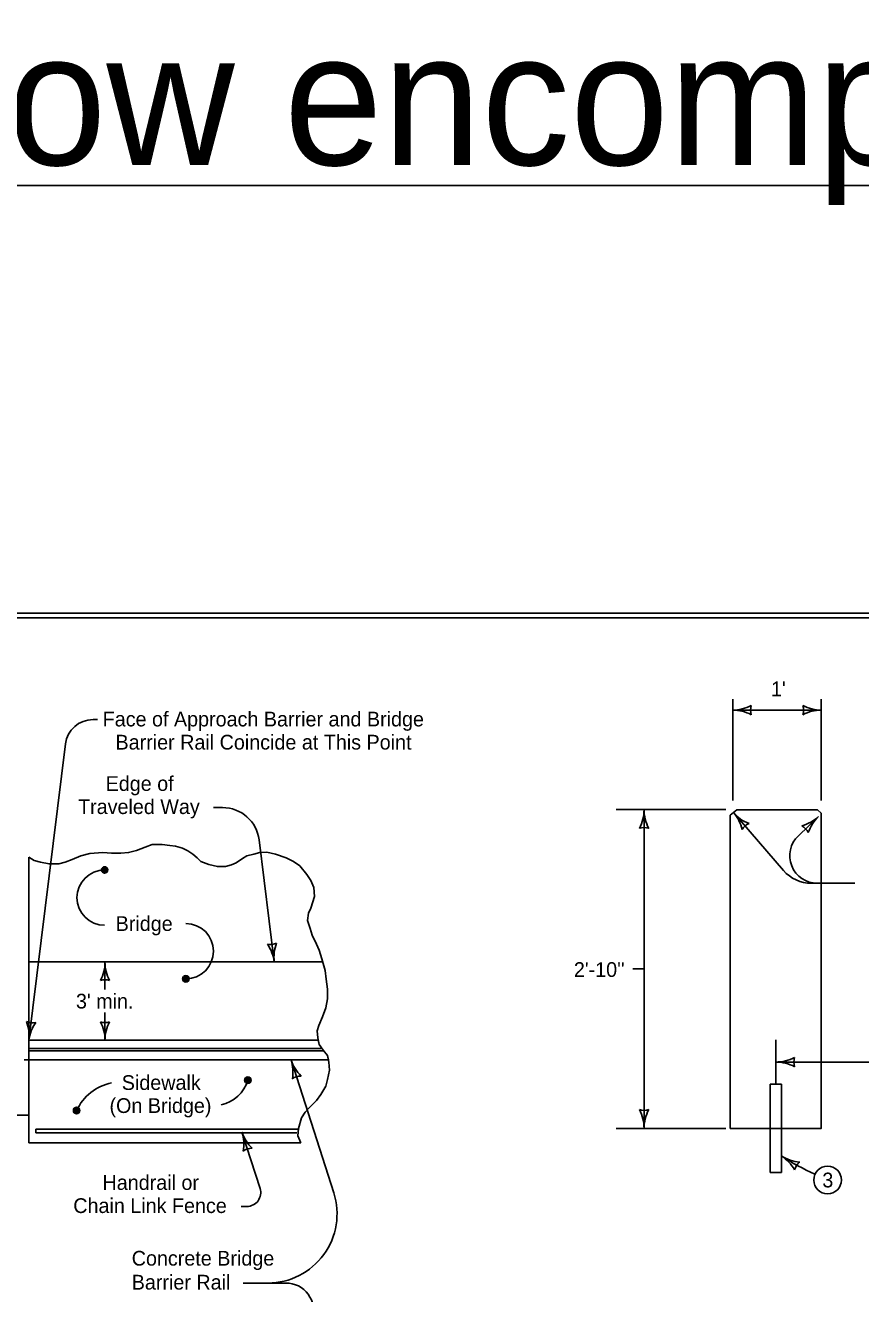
# Model space of a CAD drawing. Extents: x 10028 to 81668, y 6395 to 11634.
# Drawn here: x 11378 to 12284, y 9205 to 10582 of the extents above; entities that cross this region are included whole.
import ezdxf

# ---------------------------------------------------------------- set-up
doc = ezdxf.new("R2010")
doc.units = 0
for name, color, linetype in [('Default', 7, 'Continuous'), ('dsnCellElements', 7, 'Continuous'), ('dsnstdblockInterim', 7, 'Continuous'), ('dsnStdDimension', 7, 'Continuous'), ('dsnStdTextLabel', 7, 'Continuous'), ('ShtPlotIdentification', 7, 'Continuous')]:
    doc.layers.add(name, color=color, linetype=linetype)

msp = doc.modelspace()

# ---------------------------------------------------------------- linework, layer by layer
at = {"layer": 'Default'}
msp.add_lwpolyline([(10132.5, 9944), (13267.5, 9944), (13267.5, 7924), (10132.5, 7924)], close=True, dxfattribs=at)
msp.add_lwpolyline([(10132.5, 9944), (13267.5, 9944), (13267.5, 7924), (10132.5, 7924)], close=True, dxfattribs=at)
at = {"layer": 'dsnCellElements'}
for p, q in [((11381.7, 9459.2), (11381.7, 9480.5)), ((11381.7, 9480.5), (11695.7, 9480.5)), ((11706.6, 9459.2), (11381.7, 9459.2))]:
    msp.add_line(p, q, dxfattribs=at)
msp.add_lwpolyline([(12142.6, 9384.9), (12241.3, 9384.9), (12241.3, 9727), (12237.1, 9730.6), (12149.5, 9730.6), (12142.6, 9724.7)], close=True, dxfattribs=at)
msp.add_lwpolyline([(11695.7, 9480.5), (11696.7, 9476.1), (11700.8, 9469.7), (11705.5, 9463.9), (11706.6, 9459.2)], dxfattribs=at)
at = {"layer": 'dsnstdblockInterim'}
for points in [[(10132.5, 9944), (13267.5, 9944), (13267.5, 7924), (10132.5, 7924)], [(10132.5, 9939), (13267.5, 9939), (13267.5, 7929), (10132.5, 7929)]]:
    msp.add_lwpolyline(points, close=True, dxfattribs=at)
at = {"layer": 'dsnStdDimension'}
msp.add_lwpolyline([(10028, 7824.5), (13372, 7824.5), (13372, 10408.5), (10028, 10408.5)], close=True, dxfattribs=at)
at = {"layer": 'ShtPlotIdentification'}
for p, q in [((12145.3, 9740.9), (12145.3, 9850.9)), ((12241.3, 9740.9), (12241.3, 9850.9)), ((12241.3, 9838.9), (12145.3, 9838.9)), ((11456, 9828.6), (11451.3, 9828.6)), ((11381.7, 9480.5), (11421.6, 9802.3)), ((11591.8, 9733.1), (11582, 9733.1)), ((12137.9, 9730.9), (12018.9, 9730.9)), ((12049, 9384.9), (12049, 9730.9)), ((12142.6, 9724.7), (12149.5, 9730.6)), ((12142.6, 9384.9), (12142.6, 9724.7)), ((12146.1, 9727.7), (12200.3, 9664.8)), ((12237.1, 9730.6), (12149.5, 9730.6)), ((12238.2, 9723.4), (12216.4, 9702.6)), ((12241.3, 9727), (12237.1, 9730.6)), ((12241.3, 9384.9), (12241.3, 9727)), ((11647.9, 9565.5), (11631.5, 9698.1)), ((11381.7, 9679.2), (11381.7, 9459.2)), ((11381.7, 9679.2), (11381.7, 9459.2)), ((12277.7, 9650.9), (12230.6, 9650.9)), ((11381.7, 9565.5), (11700.6, 9565.5)), ((11464.3, 9535.5), (11464.3, 9565.5)), ((12049, 9557.9), (12037, 9557.9)), ((11464.3, 9480.5), (11464.3, 9510.5)), ((11381.7, 9480.5), (11695.7, 9480.5)), ((12192, 9480.9), (12192, 9432.9)), ((11376.7, 9459.2), (11706.6, 9459.2)), ((11381.7, 9471.7), (11698.4, 9471.7)), ((11381.7, 9469.2), (11700.9, 9469.2)), ((11381.7, 9369.2), (11381.7, 9459.2)), ((11666.2, 9459.2), (11712.4, 9314.9)), ((12306, 9456.9), (12192, 9456.9)), ((12186, 9432.9), (12198, 9432.9)), ((12186, 9432.9), (12186, 9336.9)), ((12198, 9432.9), (12198, 9336.9)), ((10687.5, 9399.2), (11381.7, 9399.2)), ((11389.2, 9384.2), (11674, 9384.2)), ((11389.2, 9380.2), (11389.2, 9384.2)), ((11389.2, 9380.2), (11672.3, 9380.2)), ((11612.9, 9380.8), (11632.5, 9319.7)), ((12137.9, 9384.9), (12018.9, 9384.9)), ((12142.6, 9384.9), (12241.3, 9384.9)), ((11381.7, 9369.2), (11676.7, 9369.2)), ((12186, 9336.9), (12198, 9336.9)), ((11612.1, 9300.1), (11618.2, 9300.1)), ((11660.5, 9217), (11614.1, 9217))]:
    msp.add_line(p, q, dxfattribs=at)
for points in [[(11676.7, 9369.2), (11673.5, 9376.7), (11674.1, 9384.8), (11677.6, 9396.5), (11681.6, 9402.3), (11686.9, 9408.1), (11693.8, 9415.1), (11698.5, 9421.5), (11703.7, 9430.8), (11705.5, 9437.8), (11707.8, 9448.2), (11707.2, 9456.9), (11705.5, 9463.9), (11700.8, 9469.7), (11696.7, 9476.1), (11695, 9483.1), (11694.4, 9490.7), (11696.2, 9496.5), (11700.2, 9505.8), (11703.7, 9515.7), (11705.5, 9525.5), (11705.5, 9536), (11704.3, 9547), (11703.1, 9556.3), (11699.6, 9569.1), (11696.7, 9578.4), (11693.8, 9584.8), (11689.2, 9594.7), (11686.9, 9601.7), (11684, 9610.4), (11685.1, 9618.5), (11687.4, 9623.8), (11691.5, 9636.6), (11690.9, 9646.5), (11687.4, 9654), (11683.4, 9660.4), (11675.8, 9669.7), (11668.8, 9674.4), (11660.7, 9678.4), (11649.1, 9682.5), (11639.8, 9684.8), (11632.2, 9684.2), (11625.8, 9682.5), (11618.3, 9680.8), (11613.6, 9677.8), (11606.6, 9673.2), (11601.4, 9670.9), (11595, 9669.1), (11586.3, 9669.1), (11577, 9671.5), (11568.3, 9674.4), (11564.2, 9678.4), (11559.5, 9682.5), (11554.3, 9686), (11548.5, 9688.9), (11540.9, 9691.2), (11534.5, 9691.8), (11526.4, 9693), (11515.4, 9693), (11507.8, 9690.1), (11498.5, 9686.6), (11489.8, 9684.2), (11481.6, 9683.7), (11471.2, 9683.7), (11461.9, 9684.2), (11447.9, 9683.1), (11438, 9680.8), (11428.7, 9676.7), (11421.2, 9673.8), (11414.2, 9672), (11403.7, 9672), (11394.4, 9673.8), (11387.5, 9675.5), (11381.7, 9679.2)], [(11463.7, 9662.2), (11464.9, 9662.8), (11466.7, 9663.3), (11467, 9665.2), (11466.8, 9666.8), (11465.6, 9668.3), (11463.9, 9668.2), (11462, 9667.9), (11461.1, 9666.5), (11461, 9664.9), (11462.1, 9662.9), (11463.4, 9662.7), (11465.3, 9663.2), (11466.8, 9664.4), (11466.7, 9666.1), (11465.5, 9667.5), (11463.9, 9667.7), (11462, 9667.3), (11461.8, 9666.3), (11461.4, 9665), (11462.3, 9663.5), (11463.6, 9663.5), (11465.1, 9663.8), (11466.2, 9664.6), (11465.7, 9666.2), (11464.5, 9667.1), (11463, 9667.1), (11462.6, 9666.3), (11462.1, 9665.4), (11462.9, 9664.1), (11464, 9663.9), (11465, 9664.4), (11465.1, 9665.5), (11464.5, 9666.3), (11463.5, 9666.6), (11463, 9666.2), (11462.7, 9665.6), (11463.3, 9664.7), (11464, 9664.5), (11464.7, 9664.9), (11464.6, 9665.5), (11464, 9665.9), (11463.3, 9665.9), (11463.3, 9665.4), (11464, 9665.1)], [(11551.7, 9544), (11552.9, 9544.5), (11554.7, 9545.1), (11555.1, 9547), (11554.8, 9548.6), (11553.7, 9550.1), (11551.9, 9550), (11550.1, 9549.7), (11549.2, 9548.2), (11549, 9546.7), (11550.1, 9544.7), (11551.5, 9544.5), (11553.3, 9545), (11554.8, 9546.1), (11554.8, 9547.9), (11553.6, 9549.3), (11551.9, 9549.5), (11550.1, 9549.1), (11549.8, 9548.1), (11549.4, 9546.8), (11550.3, 9545.3), (11551.6, 9545.3), (11553.2, 9545.6), (11554.3, 9546.4), (11553.7, 9548), (11552.6, 9548.9), (11551, 9548.9), (11550.6, 9548.1), (11550.2, 9547.1), (11550.9, 9545.9), (11552, 9545.7), (11553.1, 9546.2), (11553.1, 9547.3), (11552.6, 9548.1), (11551.6, 9548.4), (11551.1, 9548), (11550.8, 9547.4), (11551.3, 9546.5), (11552, 9546.3), (11552.7, 9546.7), (11552.6, 9547.3), (11552.1, 9547.7), (11551.4, 9547.7), (11551.4, 9547.2), (11552, 9546.9)], [(11618.9, 9434), (11620.1, 9434.5), (11622, 9435.1), (11622.3, 9436.9), (11622.1, 9438.6), (11620.9, 9440.1), (11619.1, 9439.9), (11617.3, 9439.7), (11616.4, 9438.2), (11616.3, 9436.7), (11617.3, 9434.6), (11618.7, 9434.5), (11620.5, 9434.9), (11622, 9436.1), (11622, 9437.8), (11620.8, 9439.3), (11619.2, 9439.4), (11617.3, 9439.1), (11617, 9438), (11616.7, 9436.8), (11617.5, 9435.2), (11618.9, 9435.3), (11620.4, 9435.5), (11621.5, 9436.4), (11621, 9437.9), (11619.8, 9438.8), (11618.2, 9438.9), (11617.9, 9438), (11617.4, 9437.1), (11618.1, 9435.9), (11619.3, 9435.6), (11620.3, 9436.2), (11620.4, 9437.3), (11619.8, 9438.1), (11618.8, 9438.4), (11618.3, 9437.9), (11618, 9437.3), (11618.5, 9436.4), (11619.3, 9436.2), (11620, 9436.7), (11619.8, 9437.3), (11619.3, 9437.7), (11618.6, 9437.6), (11618.6, 9437.1), (11619.2, 9436.8)], [(11433.2, 9401.1), (11434.4, 9401.6), (11436.2, 9402.2), (11436.6, 9404.1), (11436.3, 9405.7), (11435.1, 9407.2), (11433.4, 9407.1), (11431.5, 9406.8), (11430.7, 9405.3), (11430.5, 9403.8), (11431.6, 9401.8), (11432.9, 9401.6), (11434.8, 9402.1), (11436.3, 9403.2), (11436.2, 9405), (11435.1, 9406.4), (11433.4, 9406.5), (11431.6, 9406.2), (11431.3, 9405.1), (11430.9, 9403.9), (11431.8, 9402.4), (11433.1, 9402.4), (11434.7, 9402.7), (11435.8, 9403.5), (11435.2, 9405), (11434, 9405.9), (11432.5, 9406), (11432.1, 9405.2), (11431.6, 9404.2), (11432.4, 9403), (11433.5, 9402.7), (11434.5, 9403.3), (11434.6, 9404.4), (11434.1, 9405.2), (11433, 9405.5), (11432.5, 9405.1), (11432.2, 9404.4), (11432.8, 9403.5), (11433.5, 9403.4), (11434.2, 9403.8), (11434.1, 9404.4), (11433.6, 9404.8), (11432.8, 9404.8), (11432.9, 9404.3), (11433.5, 9404)]]:
    msp.add_lwpolyline(points, dxfattribs=at)
for centre, radius in [((11463.9, 9665.4), 3.5), ((11552, 9547.2), 3.5), ((11619.2, 9437.2), 3.5), ((11433.5, 9404.3), 3.5), ((12248.1, 9328.8), 15)]:
    msp.add_circle(centre, radius, dxfattribs=at)
for centre, radius, start, end in [((12145.3, 9881.4), 42.5, 270, 298.0725), ((12180.9, 9838.9), 16.4, 162.2666, 197.7334), ((12205.7, 9838.9), 16.4, 342.2666, 17.7333), ((12241.3, 9881.4), 42.5, 241.9275, 270), ((12205.7, 9838.9), 16.4, 342.2666, 17.7333), ((12241.3, 9881.4), 42.5, 241.9275, 270), ((12145.3, 9796.4), 42.5, 61.9275, 90), ((12241.3, 9796.4), 42.5, 90, 118.0725), ((12241.3, 9796.4), 42.5, 90, 118.0725), ((11451.3, 9798.6), 30, 90, 172.9389), ((11591.8, 9693.1), 40, 7.0863, 90), ((12005.8, 9730.9), 43.2, 331.9275, 360), ((12092.2, 9730.9), 43.2, 180, 208.0725), ((12178.2, 9755.4), 42.5, 220.7841, 248.8566), ((12113.9, 9699.9), 42.5, 12.7117, 40.7841), ((12208.9, 9754.2), 42.5, 285.539, 313.6115), ((12208.9, 9754.2), 42.5, 285.539, 313.6115), ((12267.5, 9692.6), 42.5, 133.6115, 161.684), ((12267.5, 9692.6), 42.5, 133.6115, 161.684), ((12049, 9694.7), 16.7, 72.2666, 107.7334), ((12169.3, 9700.7), 16.4, 113.0508, 148.5175), ((12212.4, 9698.8), 16.4, 25.8781, 61.3448), ((12212.4, 9698.8), 16.4, 25.8781, 61.3448), ((12237.1, 9680.9), 30, 133.611, 270), ((11463.9, 9635.4), 30, 90, 270), ((12230.6, 9690.9), 40, 220.7852, 270), ((11552, 9577.2), 30, 270, 90), ((11643.5, 9600.8), 16.4, 259.353, 294.8197), ((11605.8, 9560.2), 42.5, 7.0863, 35.1588), ((11690.1, 9570.7), 42.5, 159.0138, 187.0863), ((11421.8, 9565.5), 42.5, 331.9275, 360), ((11506.8, 9565.5), 42.5, 180, 208.0725), ((11464.3, 9529.8), 16.4, 72.2666, 107.7334), ((11386.1, 9515.8), 16.4, 245.2055, 280.6722), ((11339.5, 9485.7), 42.5, 352.9389, 21.0113), ((11423.9, 9475.3), 42.5, 144.8664, 172.9389), ((11464.3, 9516.1), 16.4, 252.2666, 287.7333), ((11421.8, 9480.5), 42.5, 360, 28.0725), ((11506.8, 9480.5), 42.5, 151.9275, 180), ((11706.6, 9472.2), 42.5, 197.7772, 225.8497), ((11625.7, 9446.3), 42.5, 349.7047, 17.7772), ((11706.6, 9472.2), 42.5, 197.7772, 225.8497), ((11625.7, 9446.3), 42.5, 349.7047, 17.7772), ((12192, 9500.1), 43.2, 270, 298.0725), ((12228.2, 9456.9), 16.7, 162.2666, 197.7334), ((12192, 9413.7), 43.2, 61.9275, 90), ((11482.3, 9381.6), 53.8, 101.6258, 155.0644), ((11581.2, 9449), 39.8, 283.3414, 342.7383), ((11677, 9425.3), 16.4, 90.0438, 125.5105), ((11677, 9425.3), 16.4, 90.0438, 125.5105), ((12049, 9421.1), 16.7, 252.2666, 287.7333), ((12005.8, 9384.9), 43.2, 360, 28.0725), ((12092.2, 9384.9), 43.2, 151.9275, 180), ((11653.4, 9393.8), 42.5, 197.7772, 225.8497), ((11572.5, 9367.8), 42.5, 349.7047, 17.7772), ((11623.8, 9346.9), 16.4, 90.0438, 125.5105), ((12350.9, 9592.5), 282.5, 237.2137, 245.6519), ((12221.4, 9391.3), 43.2, 237.2137, 265.2862), ((12174.6, 9318.7), 43.2, 29.1412, 57.2137), ((12228.4, 9335.4), 16.7, 129.4803, 164.947), ((11618.2, 9315.1), 15, 270, 17.7773), ((11641, 9292), 75, 270, 17.7772), ((11660.5, 9187), 30, 342.7953, 90)]:
    msp.add_arc(centre, radius, start, end, dxfattribs=at)

# ---------------------------------------------------------------- texts
at = {"layer": 'dsnCellElements'}
for s, p in [("1'", (12186.7, 9854)), ('Face of Approach Barrier and Bridge', (11461.8, 9821.2)), ('Barrier Rail Coincide at This Point', (11475.7, 9796.1)), ('Edge of', (11465, 9751.2)), ('Traveled Way', (11435.1, 9726.1)), ('Bridge', (11475.9, 9599.2)), ("2'-10''", (11972.9, 9549.3)), ("3' min.", (11432.8, 9515)), ('Sidewalk', (11482.5, 9426.6)), ('(On Bridge)', (11469.2, 9401.6)), ('Handrail or', (11461.6, 9318.1)), ('Chain Link Fence', (11429.9, 9293)), ('Concrete Bridge', (11493.3, 9235.9)), ('Barrier Rail', (11493.3, 9209.9))]:
    msp.add_text(s, height=16, dxfattribs=at).set_placement(p)
at = {"layer": 'dsnStdTextLabel'}
msp.add_text('The boxes below encompass the usable area within the print border.', height=144, dxfattribs=at).set_placement((10149.1, 10430.6))
at = {"layer": 'ShtPlotIdentification'}
msp.add_text('3', height=16, dxfattribs=at).set_placement((12242.4, 9320.8))

doc.saveas('drawing.dxf')
